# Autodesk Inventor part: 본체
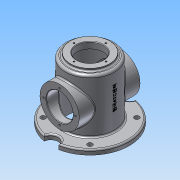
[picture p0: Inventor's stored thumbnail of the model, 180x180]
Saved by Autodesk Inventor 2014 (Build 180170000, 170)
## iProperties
Created: 2018-04
Part Number: 본체
Material: 알루미늄 6061
Document SubType Name: Modeling
Designer: NET
Density: 2.71 g/cm^3
Appearance: 알루미늄 - 평지
Mass: 1151.48 g
Surface Area: 1200.97 cm^2
Volume: 424.901 cm^3
Author: NET
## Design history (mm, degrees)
sketch "스케치1"
  geometry: L1 (0, 0)-(0, 133); L2 (0, 133)-(40, 133); L3 (40, 133)-(40, 128); L4 (40, 128)-(50, 128); L5 (50, 128)-(50, 0); L6 (50, 0)-(0, 0); L7 (27, 120)-(45, 120); L8 (45, 120)-(45, 0); L9 (0, 133)-(27, 133); L10 (27, 120)-(27, 133)
  constraints: 20 end point, 5 perpendicular, 2 parallel, 2 point on line, 1 vertical
  dimensions: "d0" = 133 distance of L1.start L1.end; "d1" = 80 diameter of L3 L1; "d2" = 100 diameter of L5 L1; "d4" = 5 distance of L2.end L3.end; "d12" = 90 diameter of L8 L1; "d14" = 13 distance of L7.start L9.end; "d15" = 54 diameter of L10 L1; "d16" = 120 distance of L7.end L8.end
revolve "회전1" stored, may be unused: angle "d5" = 90 deg
sketch "스케치2"
  geometry: L1 (-40, 133)-(40, 133) reference; L2 (-62, 68)-(62, 68); L3 (-50, 0)-(50, 0) reference; L4 (-62, 68)-(-62, 108); L5 (-62, 108)-(62, 108); L6 (62, 108)-(62, 68); 3 further points
  constraints: 8 end point, 2 midpoint, 2 parallel, 2 perpendicular, 1 vertical alignment
  dimensions: "d6" = 68 distance between parallel lines of L3 L2; "d7" = 124 distance of L2.start L2.end; "d8" = 80 diameter of L5 L2
revolve "회전2" sketch "스케치2" stored, may be unused: angle "d9" = 90 deg
fillet "모깎기1" dims "d10" = 5
revolve "회전3" stored, may be unused: angle "d17" = 90 deg
hole "구멍1" diameter "d20" = 54; stored, may be unused: countersink angle "d24" = 90 deg, drill point angle "d26" = 118 deg; dims "d18" = 10, "d19" = 10, "d21" = 6, "d22" = 4, "d23" = 2, "d25" = 8
sketch "스케치3" dims "d27" = 65
  geometry: C1 r 27 at (0, 0) reference; C2 r 40 at (0, 0) reference; 2 further points
  constraints: 2 vertical alignment, 1 coincident, 2 other
hole "구멍2" sketch "스케치3" at (0, 32.5) diameter "d28" = 3.242; stored, may be unused: countersink angle "d32" = 90 deg, drill point angle "d34" = 118 deg; dims "d29" = 8, "d30" = 4, "d31" = 2, "d33" = 10
sketch "스케치4" dims "d38" = 65
  geometry: C1 r 27 at (0, 0) reference; C2 r 40 at (0, 0) reference; 3 further points
  constraints: 2 vertical alignment, 1 coincident, 2 other
hole "구멍3" sketch "스케치4" at (0, 32.5) diameter "d39" = 3.242; stored, may be unused: countersink angle "d43" = 90 deg, drill point angle "d45" = 118 deg; dims "d40" = 8, "d41" = 4, "d42" = 2, "d44" = 10
chamfer "모따기1" distance "d49" = 1; stored, may be unused: second distance "d50" = 2, angle "d51" = 45 deg
fillet "모깎기2" dims "d52" = 3
fillet "모깎기3" dims "d53" = 3
fillet "모깎기4" dims "d54" = 3
chamfer "모따기2" distance "d55" = 1; stored, may be unused: second distance "d56" = 2, angle "d57" = 45 deg
node "작업 평면1"
sketch "스케치5"
  geometry: C1 r 15 at (0, -80); C2 r 15 at (0, 80); C3 r 45 at (0, 0); A1 r 80 centre (0, 0) between (0, -80) and (0, 80); 1 further point
  constraints: 4 centre point, 2 coincident, 2 point on circle, 2 vertical alignment
  dimensions: "d59" = 160 diameter of A1; "d61" = 30 diameter of C1; "d62" = 30 diameter of C2; "d79" = 90 diameter of C3
extrude "돌출1" join sketch "스케치5" distance "d63" = 10; taper "d64" = 0 deg
extrude "돌출2" cut sketch "스케치5" distance "d65" = 10; taper "d66" = 0 deg
extrude "돌출3" cut sketch "스케치5" distance "d67" = 10; taper "d68" = 0 deg
sketch "스케치6"
  geometry: L1 (0, 0)-(0, 67.5); L2 (0, 0)-(-47.73, 47.73); C1 r 50 at (0, 0) reference; A1 r 67.5 centre (0, 0) between (0, 67.5) and (-47.73, 47.73); 1 further point
  constraints: 4 end point, 2 coincident, 2 point on circle, 1 centre point, 1 vertical
  dimensions: "d69" = 135 diameter of A1; "d70" = 45 deg angle of L2 L1
hole "구멍4" sketch "스케치6" at (-47.73, 47.73) diameter "d71" = 10; stored, may be unused: countersink angle "d75" = 90 deg, drill point angle "d77" = 118 deg; dims "d72" = 8, "d73" = 4, "d74" = 2, "d76" = 10
fillet "모깎기5" dims "d78" = 3
extrude "돌출4" cut sketch "스케치5" distance "d80" = 10; taper "d81" = 0 deg
chamfer "모따기3" distance "d82" = 1; stored, may be unused: second distance "d83" = 2, angle "d84" = 45 deg
fillet "모깎기6" dims "d85" = 3
node "작업 평면3"
sketch "스케치8"
  geometry: L1 (-78.594, 15)-(78.594, 15) reference; L2 (-78.594, 15)-(78.594, 8) reference; L3 (78.594, 8)-(78.594, 8) reference; L4 (78.594, 8)-(78.594, 15) reference; L5 (78.594, 8)-(78.594, 8) reference; 6 further points
  constraints: 3 point on line, 1 coincident, 1 vertical alignment, 1 other
  dimensions: "d93" = 70 distance of point (0, 8) point (0, 78)
feature "엠보싱2" sketch "스케치8" dims "d94" = 0.5, "d95" = 0
node "솔리드1"
pattern_circular "원형 패턴1" dims angle "d36" = 360 deg
pattern_circular "원형 패턴2" dims angle "d47" = 360 deg
mirror "대칭1"
mirror "대칭2"
mirror "대칭3"
node "투영된 루프2"
other parameters: "d58" = 8, "d89" = 50.5
